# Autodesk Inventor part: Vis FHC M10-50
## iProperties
Shininess: 64.0
Length Units: 11269
Angle Units: 11279
Time Units: 11290
Mass Units: 11283
Length Display Precision: 3
Angle Display Precision: 2
Compacted: True
Part Number: Vis FHC M10-50
Document SubType Name: Modeling
Created: 2006-01
Material: Par défaut
Designer: Fricot
Density: 0.0
Volumn: 0.0
Area: 0.0
PropertySet Name: Model Information
Control State: 0
Master: False
Checked Out: False
Author: Fricot
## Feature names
1. Base1
